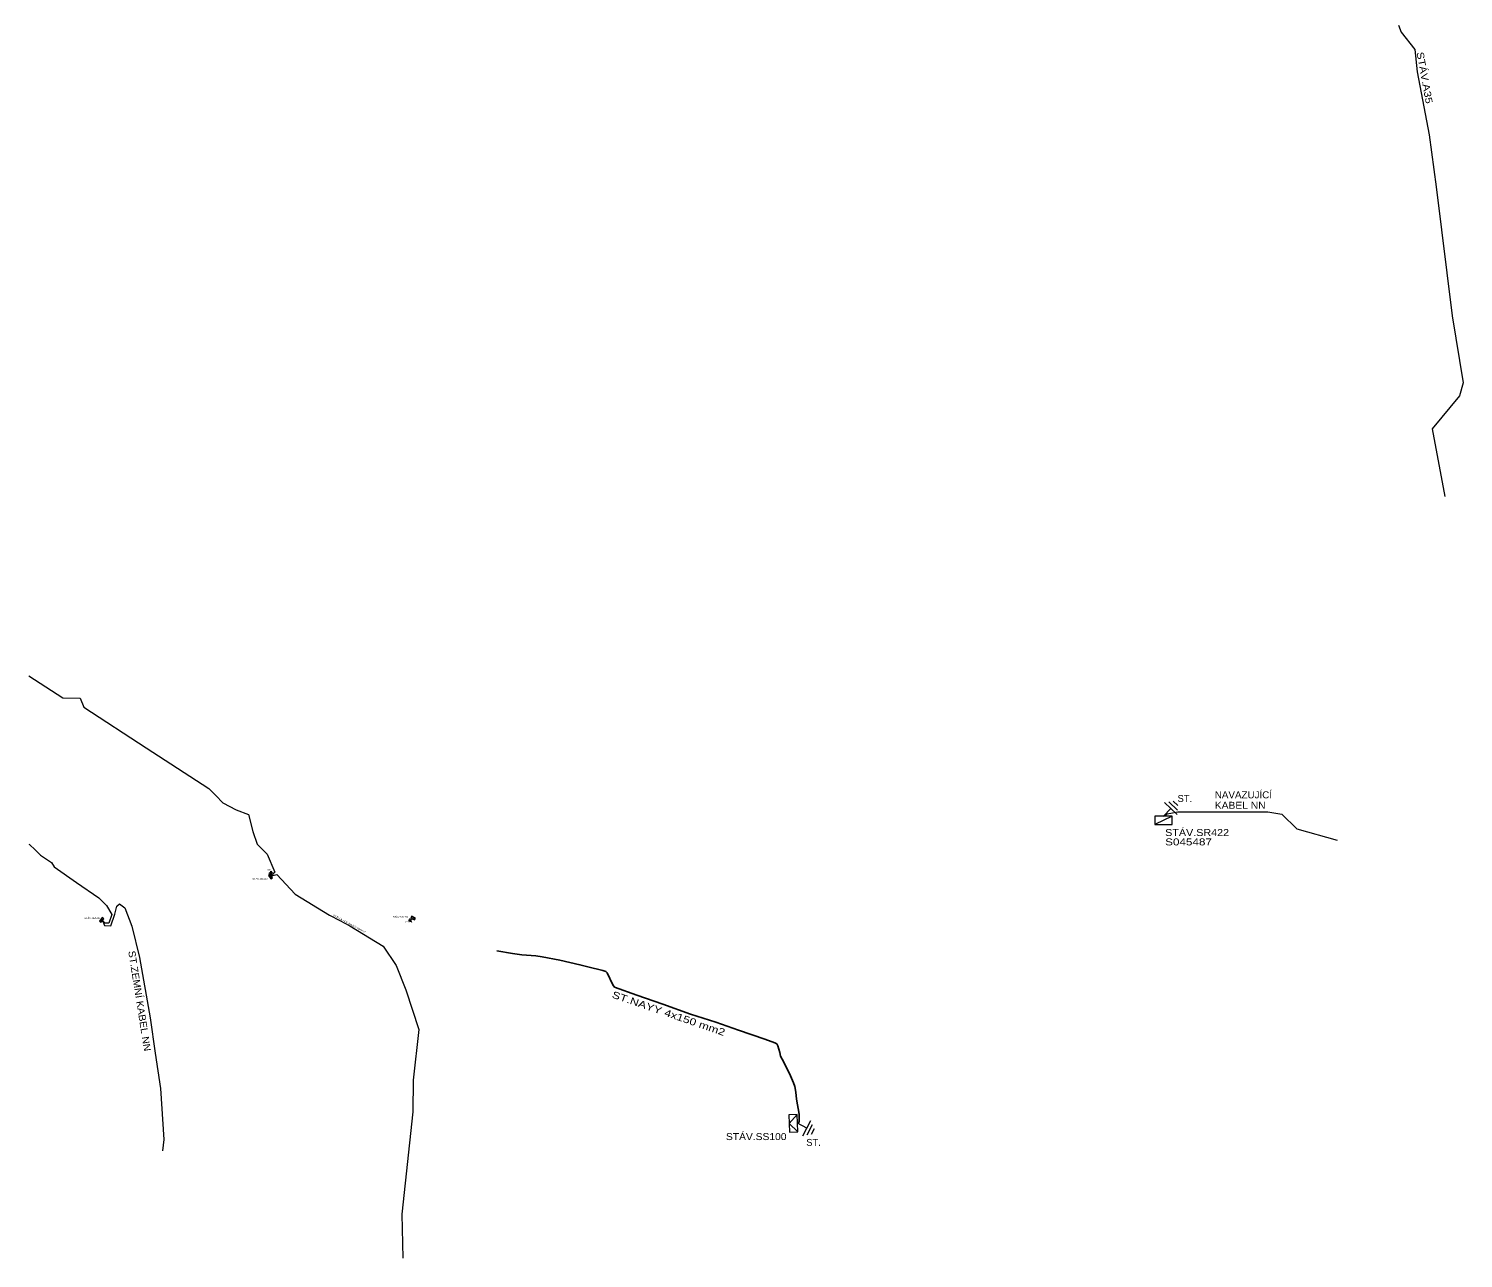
# Model space of a CAD drawing. Extents: x -787638 to -786771, y -1153867 to -1153098.
# Drawn here: x -787638.3 to -787227.6, y -1153866.7 to -1153514.6 of the extents above; entities that cross this region are included whole.
import ezdxf

# ---------------------------------------------------------------- set-up
doc = ezdxf.new("R2010")
doc.units = 0
doc.header["$LTSCALE"] = 0.8
for name, color, linetype, lineweight in [('19', 7, 'Continuous', 13), ('41', 7, 'Continuous', 13), ('50', 7, 'Continuous', 13)]:
    doc.layers.add(name, color=color, linetype=linetype, lineweight=lineweight)
doc.layers.add('20', color=7, linetype='Continuous')
doc.layers.add('42', color=7, linetype='Continuous')

msp = doc.modelspace()

# ---------------------------------------------------------------- linework, layer by layer
at = {"layer": '19'}
for p, q in [((-787310.898, -1153740.096), (-787315.898, -1153742.496)), ((-787617.498, -1153770.512), (-787617.273, -1153769.144))]:
    msp.add_line(p, q, dxfattribs=at)
for points in [[(-787310.898, -1153740.096), (-787315.898, -1153740.096), (-787315.898, -1153742.496), (-787310.898, -1153742.496)], [(-787569.633, -1153757.068), (-787568.932, -1153758.103), (-787568.436, -1153757.767), (-787569.136, -1153756.731)], [(-787617.498, -1153770.512), (-787616.781, -1153769.488), (-787617.273, -1153769.144), (-787617.99, -1153770.168)], [(-787527.511, -1153769.279), (-787528.625, -1153768.712), (-787528.897, -1153769.246), (-787527.783, -1153769.814)], [(-787420.689, -1153825.665), (-787420.469, -1153830.66), (-787418.071, -1153830.555), (-787418.291, -1153825.559)]]:
    msp.add_lwpolyline(points, close=True, dxfattribs=at)
for points in [[(-787569.136, -1153756.731), (-787569.283, -1153757.585), (-787568.436, -1153757.767)], [(-787527.783, -1153769.814), (-787528.068, -1153768.995), (-787528.897, -1153769.246)], [(-787418.291, -1153825.559), (-787420.579, -1153828.162), (-787418.071, -1153830.555)]]:
    msp.add_lwpolyline(points, dxfattribs=at)
at = {"layer": '41'}
for points in [[(-787246.14, -1153513.56), (-787245.4, -1153515.57), (-787241.41, -1153520.49), (-787240.79, -1153526.97), (-787237.38, -1153544.99), (-787235.33, -1153559.885), (-787230.74, -1153596.82), (-787227.58, -1153616), (-787228.63, -1153619.68), (-787236.52, -1153629.22), (-787232.822, -1153648.606)], [(-787638.271, -1153699.875), (-787628.465, -1153706.201), (-787623.5, -1153706.3), (-787622.503, -1153708.87), (-787604.617, -1153720.51), (-787586.73, -1153732.15), (-787584.71, -1153734.24), (-787582.69, -1153736.33), (-787578.91, -1153738.29), (-787575.32, -1153739.62), (-787574.1, -1153744.46), (-787572.91, -1153748.11), (-787570, -1153750.96), (-787567.85, -1153756.16), (-787568.786, -1153757.249)], [(-787313.398, -1153740.096), (-787312.356, -1153739.397), (-787309.264, -1153738.876), (-787283.531, -1153738.876), (-787279.54, -1153739.571), (-787275.217, -1153743.77), (-787263.679, -1153746.942)], [(-787638.196, -1153748.134), (-787638.01, -1153748.25), (-787636.445, -1153749.78), (-787634.88, -1153751.31), (-787631.77, -1153753.42), (-787631, -1153754.67), (-787624.61, -1153759.09), (-787618.22, -1153763.51), (-787616.02, -1153765.73), (-787614.494, -1153768.302), (-787615.372, -1153770.727), (-787616.403, -1153770.795), (-787617.118, -1153769.984)], [(-787568.786, -1153757.249), (-787567.25, -1153756.8), (-787562.01, -1153762.41), (-787552.191, -1153768.437), (-787549.245, -1153769.983), (-787546.3, -1153771.53), (-787536.83, -1153777.32), (-787533.1, -1153782.91), (-787530.353, -1153789.871), (-787526.56, -1153801.18), (-787528.21, -1153815.71), (-787528.32, -1153824.8), (-787531.46, -1153854.11), (-787531.156, -1153866.748)], [(-787617.118, -1153769.984), (-787616.562, -1153771.391), (-787614.798, -1153771.491), (-787613.613, -1153768.219), (-787613.055, -1153765.925), (-787612.23, -1153765.26), (-787610.77, -1153766.33), (-787608.71, -1153771.58), (-787606.59, -1153780.55), (-787603.543, -1153797.849), (-787602.031, -1153807.98), (-787600.52, -1153818.11), (-787599.54, -1153832.73), (-787599.985, -1153835.935)]]:
    msp.add_lwpolyline(points, dxfattribs=at)
at = {"layer": '41', "lineweight": 25}
msp.add_lwpolyline([(-787504.26, -1153778.68), (-787499.76, -1153779.48), (-787497.09, -1153779.84), (-787493.09, -1153780.16), (-787491.31, -1153780.41), (-787486.22, -1153781.32), (-787480.48, -1153782.67), (-787478.16, -1153783.31), (-787473.87, -1153784.31), (-787473.08, -1153784.57), (-787472.71, -1153784.97), (-787471.02, -1153788.46), (-787470.53, -1153789.05), (-787464.15, -1153791.39), (-787456.72, -1153793.94), (-787448.84, -1153796.79), (-787441.6, -1153799.15), (-787435.05, -1153801.37), (-787427.56, -1153804.01), (-787424.67, -1153805.03), (-787424.12, -1153805.36), (-787423.83, -1153805.86), (-787423.2, -1153807.81), (-787423.05, -1153808.89), (-787422.05, -1153810.6), (-787420.23, -1153814.48), (-787419.3, -1153816.46), (-787418.99, -1153817.52), (-787418.69, -1153819.15), (-787418.47, -1153821.16), (-787417.7, -1153825.5), (-787417.67, -1153827.74), (-787418.18, -1153828.06)], dxfattribs=at)
at = {"layer": '50'}
for p, q in [((-787309.53, -1153739.632), (-787313.164, -1153736.198)), ((-787309.425, -1153738.356), (-787311.896, -1153736.02)), ((-787309.319, -1153737.08), (-787310.627, -1153735.843)), ((-787311.347, -1153737.915), (-787313.408, -1153740.095)), ((-787568.24, -1153756.434), (-787569.483, -1153756.567)), ((-787568.465, -1153756.207), (-787569.311, -1153756.297)), ((-787568.691, -1153755.98), (-787569.138, -1153756.028)), ((-787568.862, -1153756.5), (-787568.782, -1153757.247)), ((-787529.553, -1153769.916), (-787529.343, -1153770.314)), ((-787529.425, -1153769.622), (-787529.028, -1153770.374)), ((-787529.297, -1153769.328), (-787528.714, -1153770.434)), ((-787529.006, -1153769.881), (-787528.342, -1153769.531)), ((-787415.523, -1153829.454), (-787418.181, -1153828.063)), ((-787416.683, -1153831.669), (-787414.364, -1153827.239)), ((-787415.426, -1153831.424), (-787413.849, -1153828.411)), ((-787414.169, -1153831.179), (-787413.334, -1153829.584))]:
    msp.add_line(p, q, dxfattribs=at)

# ---------------------------------------------------------------- texts
at = {"layer": '20'}
for s, height, width, p in [('STÁV.SR422', 2, 1.15, (-787312.927, -1153745.805)), ('S045487', 2, 1.25, (-787312.927, -1153748.488)), ('STÁV.SS100', 0.5, 1.1, (-787574.238, -1153758.286)), ('STÁV.SR502', 0.5, 1.15, (-787622.44, -1153769.57)), ('STÁV.SS100', 0.5, 1.1, (-787534.066, -1153769.229)), ('STÁV.SS100', 2, 1.1, (-787438.662, -1153832.884))]:
    msp.add_text(s, height=height, dxfattribs=dict(at, width=width)).set_placement(p)
at = {"layer": '42'}
for s, height, rotation, width, p in [('STÁV.A35', 2, 280.283, 1.2, (-787240.957, -1153521.414)), ('STÁV.AYKY 3x120+70mm2', 0.5, 331.819, 1.25, (-787551.218, -1153768.64)), ('ST.ZEMNÍ KABEL NN', 2, 279.012, 1.1, (-787609.774, -1153778.818)), ('ST.NAYY 4x150 mm2', 2, 341.055, 1.3, (-787471.478, -1153792.047))]:
    msp.add_text(s, height=height, rotation=rotation, dxfattribs=dict(at, width=width)).set_placement(p)
for s, width, p in [('NAVAZUJÍCÍ', 1.05, (-787298.723, -1153735.001)), ('KABEL NN', 1.1, (-787298.723, -1153738.001))]:
    msp.add_text(s, height=2, dxfattribs=dict(at, width=width)).set_placement(p)
at = {"layer": '50'}
for height, p in [(2, (-787309.385, -1153736.048)), (0.5, (-787569.9, -1153755.742)), (0.5, (-787530.64, -1153770.736)), (2, (-787415.67, -1153834.549))]:
    msp.add_text('ST.', height=height, dxfattribs=at).set_placement(p)

doc.saveas('drawing.dxf')
